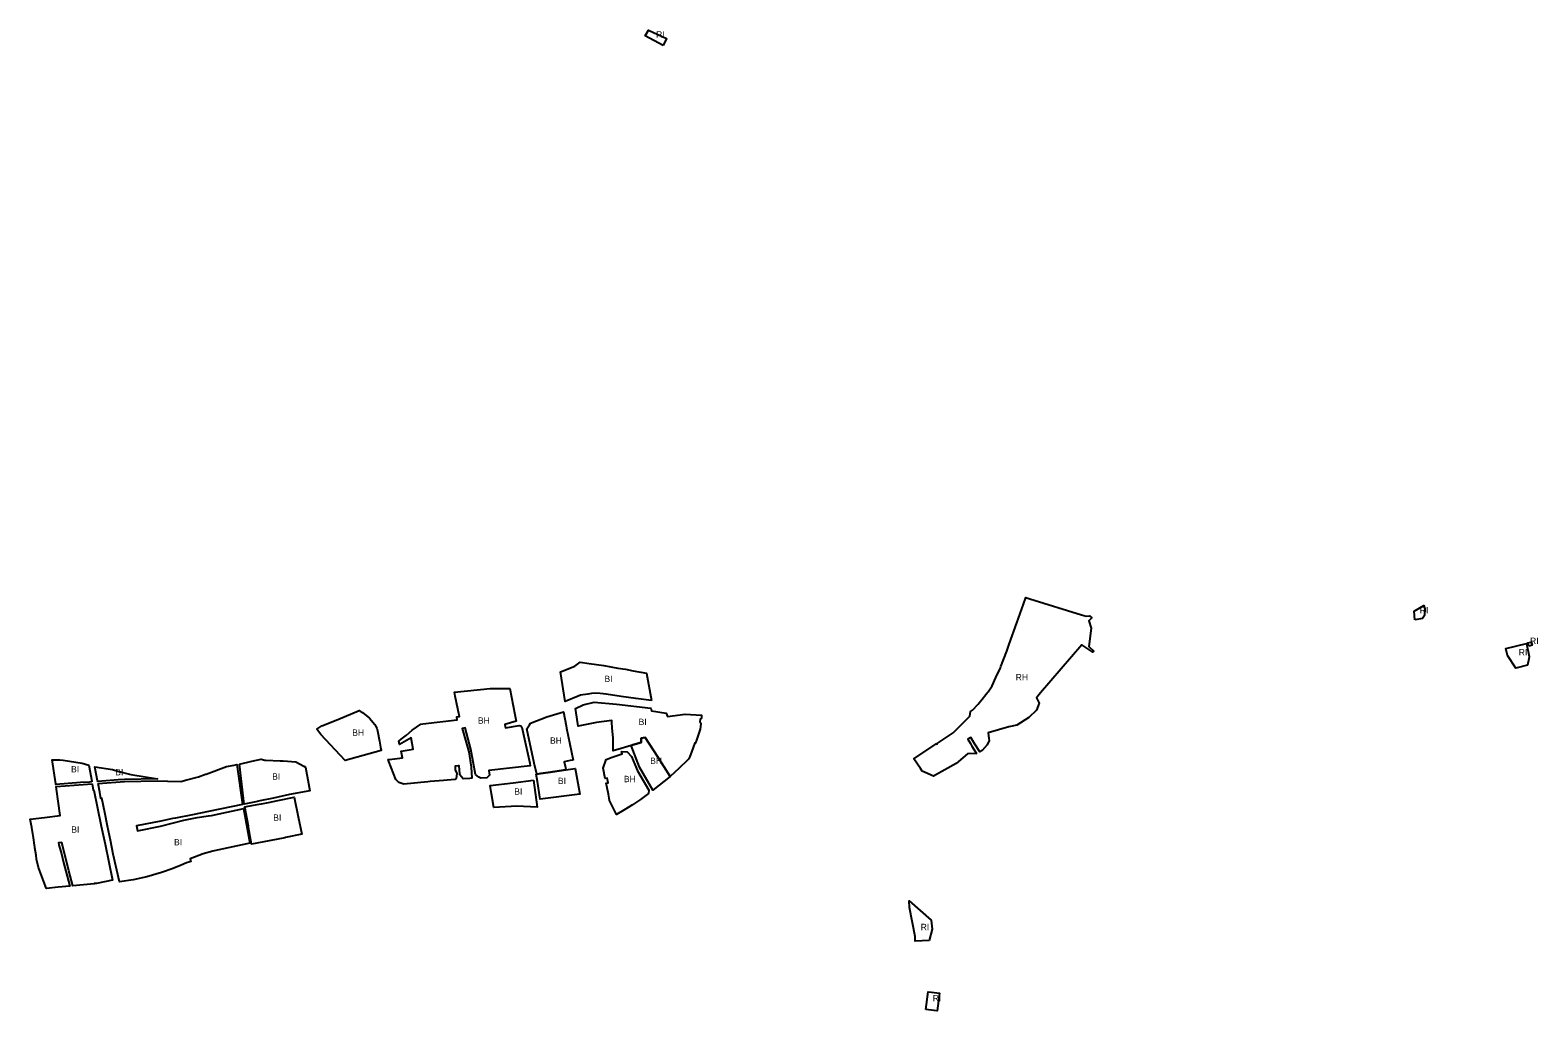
# Model space of a CAD drawing. Extents: x -477010 to -466219, y -1158799 to -1150161.
# Drawn here: x -474118 to -471985, y -1154237 to -1152850 of the extents above; entities that cross this region are included whole.
import ezdxf

# ---------------------------------------------------------------- set-up
doc = ezdxf.new("R2010")
doc.units = 0
for name, color, linetype in [('16', 7, 'Continuous'), ('19', 7, 'Continuous'), ('4', 7, 'Continuous'), ('7', 7, 'Continuous')]:
    doc.layers.add(name, color=color, linetype=linetype)

msp = doc.modelspace()

# ---------------------------------------------------------------- linework, layer by layer
at = {"layer": '16'}
msp.add_lwpolyline([(-472779.082, -1153873.426), (-472779.4, -1153873.59), (-472788.64, -1153873.41), (-472791.82, -1153873.96), (-472808.05, -1153887.4), (-472839.75, -1153905.5), (-472855.97, -1153898.08), (-472858.47, -1153894.37), (-472867.62, -1153880.8), (-472835.96, -1153859.77), (-472834.97, -1153859.91), (-472834.83, -1153859.02), (-472812.2, -1153843.99), (-472788.51, -1153820.34), (-472787.46, -1153813.96), (-472784.79, -1153812), (-472776.81, -1153803.44), (-472775.54, -1153801.47), (-472773.11, -1153798.75), (-472763.85, -1153787.43), (-472762.74, -1153786.07), (-472757.17, -1153777.83), (-472751.64, -1153766.03), (-472745.27, -1153752.08), (-472744.5, -1153750.39), (-472736.45, -1153728.34), (-472735.52, -1153725.8), (-472733.03, -1153718.82), (-472722.3, -1153688.54), (-472712.9, -1153662.01), (-472709.41, -1153652.68), (-472703.713, -1153654.449), (-472630.856, -1153677.076), (-472624.086, -1153679.179), (-472619.47, -1153678.79), (-472615.91, -1153681.49), (-472620.03, -1153685.71), (-472617.11, -1153695.8), (-472620.24, -1153722.2), (-472613.18, -1153728.53), (-472614.58, -1153729.94), (-472630.1, -1153719.47), (-472688.56, -1153787.52), (-472694.22, -1153794.66), (-472690.61, -1153802.15), (-472694.06, -1153811.94), (-472705.04, -1153822.57), (-472722.24, -1153833.06), (-472733.19, -1153835.79), (-472762.7, -1153844.06), (-472761.61, -1153852.29), (-472761.02, -1153854.73), (-472764.06, -1153860.99), (-472770.93, -1153869.23), (-472774.625, -1153871.132), (-472781.398, -1153859.967), (-472787.164, -1153850.462), (-472787.955, -1153850.942), (-472791.439, -1153853.056), (-472787.816, -1153859.029), (-472785.516, -1153862.819)], close=True, dxfattribs=at)
at = {"layer": '19'}
for points in [[(-473222.2, -1152871.75), (-473247.66, -1152858.37), (-473243, -1152850.17), (-473217.56, -1152862.11)], [(-472159.1, -1153684.03), (-472160.3, -1153671.88), (-472146.61, -1153664.01), (-472144.87, -1153668.69), (-472145.62, -1153678.15), (-472148.25, -1153682.59)], [(-471997.63, -1153736.1), (-471998.11, -1153739.42), (-471999.75, -1153748.52), (-472016.6, -1153752.66), (-472028.12, -1153734.55), (-472030.63, -1153724.84), (-472001.29, -1153717.65)], [(-471997.96, -1153721.51), (-471999.25, -1153716.94), (-471995.22, -1153715.8), (-471994.48, -1153715.6), (-471993.2, -1153720.17), (-471996.04, -1153720.97)], [(-472845.854, -1154137.618), (-472865.913, -1154138.723), (-472866.09, -1154132.18), (-472873.67, -1154091.14), (-472874.54, -1154081.71), (-472843.059, -1154109.026), (-472841.629, -1154121.776)], [(-472850.7, -1154235.23), (-472847.39, -1154210.45), (-472842.76, -1154211.06), (-472831.53, -1154212.54), (-472834.84, -1154237.32), (-472839.1, -1154236.76)]]:
    msp.add_lwpolyline(points, close=True, dxfattribs=at)
at = {"layer": '4'}
for points in [[(-473510.85, -1153819.22), (-473512.73, -1153810.01), (-473516.37, -1153792.15), (-473517.53, -1153786.44), (-473467.13, -1153781.23), (-473439.37, -1153781.57), (-473434.36, -1153806.1), (-473432.16, -1153818.03), (-473430.37, -1153827.7), (-473446.1, -1153832.41), (-473445.26, -1153836.84), (-473426.15, -1153833.63), (-473423.71, -1153834.01), (-473422.1, -1153836.23), (-473411.04, -1153886.8), (-473410.21, -1153890.6), (-473468.87, -1153897.51), (-473468.02, -1153903.86), (-473471.5, -1153907.93), (-473480.11, -1153908.17), (-473482.94, -1153906.99), (-473487.59, -1153903.1), (-473494.49, -1153867.02), (-473502.1, -1153836.91), (-473506.4, -1153837.85), (-473497.03, -1153870.86), (-473493.73, -1153892.65), (-473493.02, -1153908.17), (-473495.79, -1153908.64), (-473505.16, -1153908.95), (-473509.85, -1153903.72), (-473509.96, -1153902.17), (-473510.77, -1153890.84), (-473512.26, -1153890.95), (-473515.73, -1153891.21), (-473516.43, -1153891.26), (-473516.23, -1153896.45), (-473513.87, -1153901.82), (-473514.96, -1153908.72), (-473516.99, -1153909.93), (-473532.88, -1153911.39), (-473551.93, -1153913.08), (-473555.17, -1153913.44), (-473589.02, -1153916.82), (-473596.03, -1153914.47), (-473600.57, -1153910.15), (-473610.08, -1153884.65), (-473611.12, -1153881.86), (-473605.83, -1153881.34), (-473590.79, -1153879.36), (-473592.99, -1153870.12), (-473575.92, -1153867), (-473578.87, -1153851.06), (-473595.38, -1153860.44), (-473596.33, -1153856.08), (-473592.96, -1153853.22), (-473585.47, -1153847.15), (-473577.03, -1153840.22), (-473565.1, -1153831.71), (-473562.12, -1153831.37), (-473513.58, -1153825.82), (-473513.87, -1153821.45), (-473510.527, -1153820.803)], [(-473621.17, -1153868.55), (-473620.99, -1153869.03), (-473672.23, -1153883.1), (-473706.36, -1153846.56), (-473712.29, -1153839), (-473705.2, -1153834.3), (-473682.48, -1153825.37), (-473652.34, -1153812.43), (-473650.9, -1153813.21), (-473647.34, -1153815.14), (-473637.39, -1153823.35), (-473630.21, -1153832.18), (-473628.97, -1153834.31), (-473627.04, -1153837.61), (-473626.16, -1153841.37), (-473623.56, -1153856.03), (-473622.01, -1153864.14)], [(-473349.39, -1153882.59), (-473354.02, -1153883.38), (-473362.14, -1153885.05), (-473360.52, -1153893.23), (-473359.98, -1153896.32), (-473385.03, -1153900.13), (-473395.58, -1153901.73), (-473401.17, -1153902.58), (-473404.59, -1153886.95), (-473415.25, -1153838.28), (-473411.32, -1153832.53), (-473409.75, -1153830.22), (-473386.95, -1153821.22), (-473363.32, -1153814.36), (-473361.3, -1153824.4), (-473359.33, -1153834.24), (-473358.87, -1153837.7)], [(-473230.14, -1153877.34), (-473212.4, -1153905.82), (-473236.77, -1153925.2), (-473255.58, -1153892.75), (-473267.47, -1153862.15), (-473265.09, -1153861.21), (-473253.2, -1153857.67), (-473253.25, -1153851.57), (-473247.87, -1153850.73)], [(-473262.32, -1153888.76), (-473258.59, -1153897.85), (-473242.32, -1153925.23), (-473242.93, -1153929.9), (-473254.4, -1153938.15), (-473265.61, -1153945.73), (-473278.13, -1153953.65), (-473288.1, -1153959.63), (-473297.95, -1153939.66), (-473298.56, -1153936.59), (-473299.71, -1153930.79), (-473301.53, -1153921.66), (-473302.8, -1153915.32), (-473300.1, -1153914.79), (-473301.4, -1153908.28), (-473304.1, -1153908.81), (-473307.03, -1153894.15), (-473303.03, -1153881.74), (-473294.47, -1153878.72), (-473291.69, -1153877.74), (-473280.47, -1153873.58), (-473280.99, -1153870.35), (-473273.38, -1153871.06), (-473266.97, -1153877.74)]]:
    msp.add_lwpolyline(points, close=True, dxfattribs=at)
at = {"layer": '7'}
for points in [[(-473238.56, -1153798.46), (-473261.1, -1153795.57), (-473281.9, -1153792.51), (-473303, -1153789.58), (-473311.33, -1153788.34), (-473317.53, -1153788.14), (-473323.57, -1153788.52), (-473328.63, -1153789.29), (-473339.06, -1153790.93), (-473342.5, -1153792.45), (-473361.05, -1153799.71), (-473367.48, -1153757.98), (-473347.35, -1153749.68), (-473339.48, -1153744.35), (-473326.84, -1153746.03), (-473306.24, -1153748.96), (-473286.38, -1153752.68), (-473275.64, -1153754.24), (-473264.63, -1153756.17), (-473245.81, -1153759.74)], [(-473198.7, -1153893.17), (-473199.42, -1153893.88), (-473212.4, -1153905.82), (-473230.14, -1153877.34), (-473247.87, -1153850.73), (-473253.25, -1153851.57), (-473253.2, -1153857.67), (-473265.09, -1153861.21), (-473267.47, -1153862.15), (-473272.37, -1153863.38), (-473281.76, -1153866.31), (-473292.76, -1153869.74), (-473293.01, -1153851.68), (-473293.82, -1153841.92), (-473294.32, -1153837.68), (-473294.73, -1153828.96), (-473294.85, -1153826.47), (-473316.76, -1153829.52), (-473342.53, -1153834.53), (-473344.29, -1153822.15), (-473346.08, -1153809.55), (-473335.45, -1153804.3), (-473320, -1153800.62), (-473288.05, -1153803.68), (-473239.78, -1153809.33), (-473238.9, -1153813.1), (-473218.18, -1153816.11), (-473215.98, -1153820.92), (-473191.24, -1153817.62), (-473167.89, -1153819.15), (-473167.89, -1153823.27), (-473168.29, -1153823.22), (-473170.135, -1153824.557), (-473170.32, -1153828.57), (-473169, -1153831.42), (-473169.94, -1153839.08), (-473175.14, -1153854.27), (-473176.36, -1153858.04), (-473176.57, -1153858.68), (-473177.5, -1153858.36), (-473179.76, -1153864.69), (-473183.59, -1153875.38), (-473186.18, -1153880.87), (-473188.94, -1153883.58)], [(-474030.305, -1153913.398), (-474033.631, -1153913.64), (-474046.224, -1153914.559), (-474081.129, -1153917.106), (-474081.275, -1153916.14), (-474086.36, -1153882.45), (-474075.54, -1153882.19), (-474070.76, -1153882.91), (-474043.9, -1153886.99), (-474034.5, -1153890.02), (-474030.478, -1153912.434)], [(-473984.241, -1153910.037), (-473992.989, -1153910.675), (-474021.928, -1153912.787), (-474022.109, -1153911.823), (-474025.83, -1153891.99), (-474001.25, -1153896.15), (-473993.68, -1153898.18), (-473975.15, -1153903.14), (-473937.55, -1153909.09)], [(-474021.372, -1153915.754), (-473984.101, -1153913.035), (-473937.546, -1153912.091), (-473923.494, -1153912.339), (-473922.838, -1153912.351), (-473904.295, -1153912.687), (-473896.088, -1153910.622), (-473895.828, -1153910.557), (-473879.307, -1153906.278), (-473869.514, -1153902.702), (-473868.792, -1153902.438), (-473839.835, -1153891.887), (-473829.08, -1153889.954), (-473825.129, -1153889.106), (-473816.99, -1153945.28), (-473865.09, -1153955.58), (-473888.08, -1153959.95), (-473911.94, -1153964.61), (-473915.77, -1153965.38), (-473932.94, -1153968.82), (-473967.041, -1153975.652), (-473965.58, -1153982.7), (-473933.06, -1153976.04), (-473914.63, -1153971.41), (-473900.35, -1153967.83), (-473881.2, -1153963.82), (-473865.16, -1153961.42), (-473860.93, -1153960.79), (-473839.53, -1153956.34), (-473819.47, -1153951.9), (-473815.909, -1153951.112), (-473806.813, -1154000.189), (-473810.98, -1154001.08), (-473830.99, -1154005.36), (-473857.34, -1154011), (-473859.26, -1154011.54), (-473872.94, -1154015.36), (-473891.08, -1154022.3), (-473890.32, -1154026.23), (-473893.25, -1154027.1), (-473896.22, -1154028.19), (-473904.01, -1154031.07), (-473916.86, -1154036.22), (-473918.18, -1154036.73), (-473928.73, -1154040.78), (-473931.76, -1154041.56), (-473952.44, -1154047.9), (-473972.02, -1154052.11), (-473991.04, -1154054.95), (-474000.03, -1154015.53), (-474004.1, -1153995.73), (-474008.26, -1153976.21), (-474012.08, -1153956.62), (-474016.08, -1153936.62), (-474017.8, -1153937.04), (-474018.18, -1153934.34), (-474019.11, -1153927.81)], [(-473821.601, -1153888.362), (-473821.282, -1153888.295), (-473804.221, -1153884.092), (-473804.143, -1153884.073), (-473791.022, -1153881.229), (-473785.454, -1153882.595), (-473784.412, -1153882.638), (-473764.013, -1153883.49), (-473760.362, -1153883.49), (-473759.66, -1153883.547), (-473741.669, -1153885.009), (-473730.256, -1153891.156), (-473728.018, -1153892.55), (-473723.76, -1153915.77), (-473721.88, -1153925.98), (-473750.61, -1153931.25), (-473767.45, -1153935.02), (-473773.42, -1153936.36), (-473792.76, -1153940.37), (-473798.13, -1153941.47), (-473815.01, -1153944.88), (-473818.31, -1153916.59)], [(-473402.12, -1153902.72), (-473401.17, -1153902.58), (-473395.58, -1153901.73), (-473385.03, -1153900.13), (-473359.98, -1153896.32), (-473346.97, -1153894.38), (-473340.25, -1153930.77), (-473396.25, -1153938.12), (-473400.05, -1153912.76)], [(-474029.772, -1153916.367), (-474028.23, -1153924.96), (-474027.32, -1153925.02), (-474022.14, -1153950.5), (-474016.9, -1153976.28), (-474011.63, -1154001.47), (-474006.33, -1154026.91), (-474001.22, -1154052.34), (-474023.75, -1154057.02), (-474027.08, -1154057.21), (-474027, -1154057.46), (-474057.32, -1154060.32), (-474062.62, -1154039.46), (-474072.41, -1154000.93), (-474072.78, -1153999.73), (-474072.85, -1153998.98), (-474077.37, -1153999.56), (-474076.83, -1154002.46), (-474073.43, -1154015.43), (-474070.26, -1154027.51), (-474061.54, -1154060.75), (-474077.85, -1154062.52), (-474094.59, -1154064.22), (-474094.69, -1154063.96), (-474095.76, -1154061.1), (-474105.79, -1154034.56), (-474108.68, -1154022.96), (-474109.16, -1154017.31), (-474110.83, -1154006.56), (-474110.98, -1154005.78), (-474111.42, -1154002.87), (-474113.02, -1153992.54), (-474115.16, -1153977.86), (-474117.54, -1153966.25), (-474097.31, -1153963.82), (-474075.03, -1153961.14), (-474080.14, -1153923.66), (-474080.68, -1153920.081)], [(-473405.9, -1153910.85), (-473400.66, -1153949.07), (-473429.43, -1153947.63), (-473461.97, -1153949.52), (-473464.99, -1153930.41), (-473466.89, -1153918.36), (-473434.37, -1153914.94)], [(-473808.96, -1153976.03), (-473813.84, -1153948.94), (-473801.46, -1153946.59), (-473793.85, -1153945.14), (-473790.32, -1153944.47), (-473780.23, -1153942.47), (-473767.16, -1153939.87), (-473744.27, -1153935), (-473738.39, -1153962.69), (-473733.09, -1153987.61), (-473756.2, -1153992.3), (-473757.38, -1153992.53), (-473779.54, -1153996.81), (-473804.37, -1154001.46), (-473808.63, -1153977.84)]]:
    msp.add_lwpolyline(points, close=True, dxfattribs=at)

# ---------------------------------------------------------------- texts
at = {"layer": '16'}
msp.add_text('RH', height=9, dxfattribs=at).set_placement((-472723.6945, -1153769.927))
at = {"layer": '19'}
for p in [(-473232.279, -1152860.747), (-472152.187, -1153674.946), (-472012.191, -1153734.683), (-471996.158, -1153718.547), (-472858.011, -1154123.2318), (-472841.05, -1154223.88)]:
    msp.add_text('RI', height=9, dxfattribs=at).set_placement(p)
at = {"layer": '4'}
for p in [(-473484.2028, -1153831.1927), (-473661.9425, -1153848.241), (-473382.2935, -1153859.493), (-473240.6665, -1153888.026), (-473277.8535, -1153913.869)]:
    msp.add_text('BH', height=9, dxfattribs=at).set_placement(p)
at = {"layer": '7'}
for p in [(-473305.283, -1153772.186), (-473256.9225, -1153833.051), (-474059.712, -1153899.993), (-473997.185, -1153904.213), (-473775.236, -1153910.295), (-473371.089, -1153916.498), (-473432.796, -1153931.579), (-473773.738, -1153968.485), (-474059.318, -1153985.363), (-473914.031, -1154003.187)]:
    msp.add_text('BI', height=9, dxfattribs=at).set_placement(p)

doc.saveas('drawing.dxf')
